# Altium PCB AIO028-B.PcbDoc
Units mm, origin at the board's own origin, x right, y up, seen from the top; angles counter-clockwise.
Board outline 85 x 50 mm, 2 copper layers (TopLayer, BottomLayer); 12 components, 10 nets, 62 pads, 55 vias.
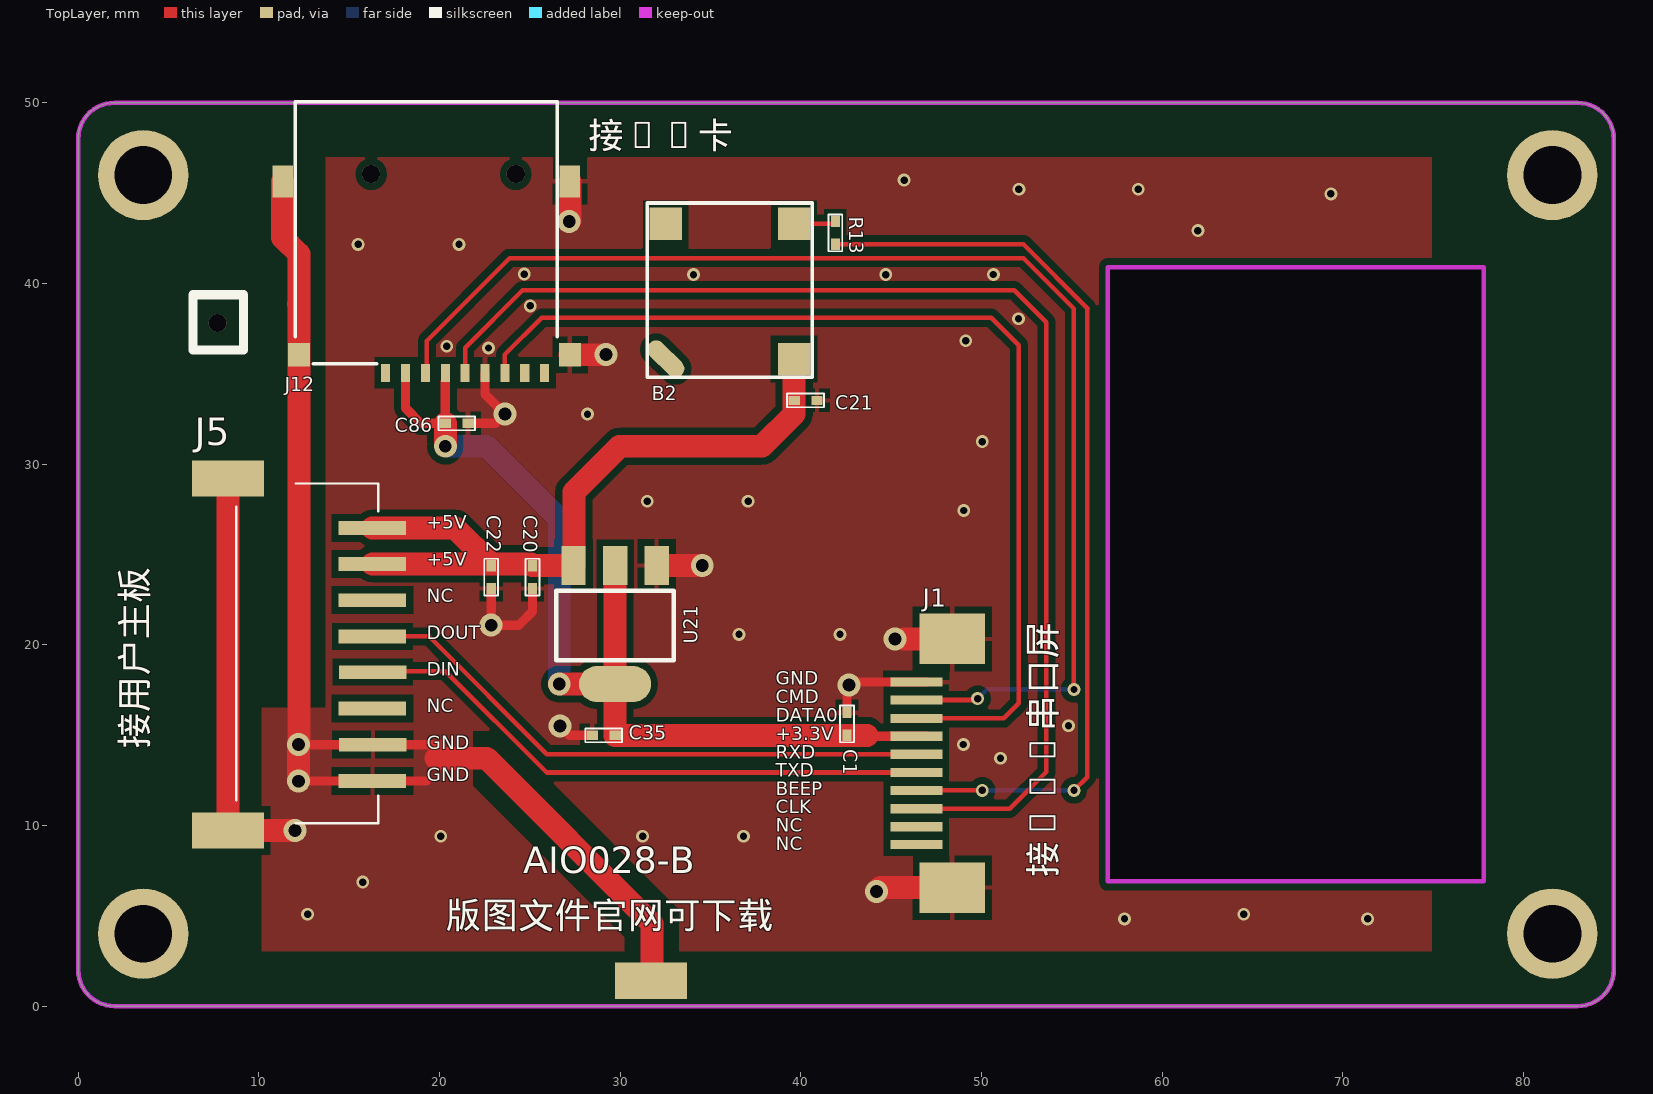
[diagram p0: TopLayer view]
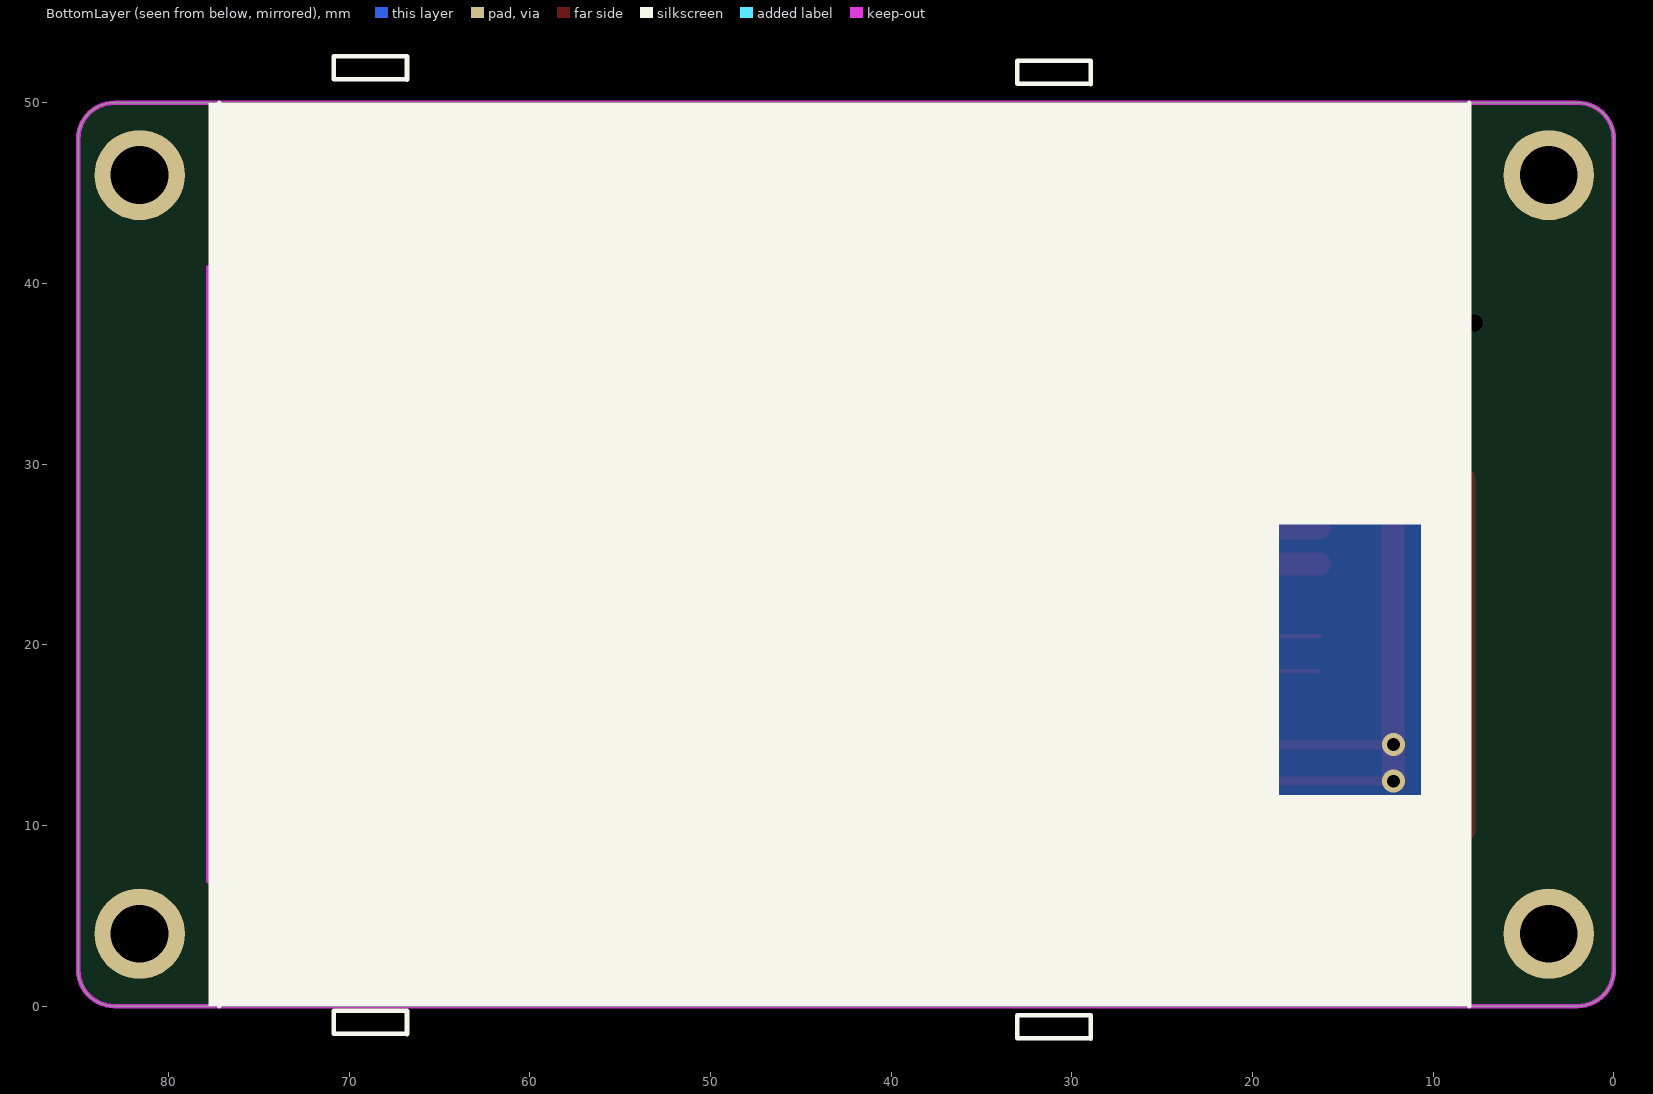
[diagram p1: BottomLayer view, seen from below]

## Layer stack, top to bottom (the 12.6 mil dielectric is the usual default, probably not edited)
TopLayer: signal copper 0.0356
Dielectric: dielectric 0.32, FR-4, Dk 4.8
BottomLayer: signal copper 0.0356

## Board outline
0,2 0,48 cw(c2,48) 2,50 83,50 cw(c83,48) 85,48 85,2 cw(c83,2) 83,0 2,0 cw(c2,2)
cut-out: 57,6.9 77.8,6.9 77.8,40.9 57,40.9

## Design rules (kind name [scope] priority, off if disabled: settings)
Clearance Clearance_polygon [InPolygon] p1: gap=0.381
Clearance [All] p2: gap=0.254
FabricationTestPointUsage TestPointUsage [All] p1: valid=0 allowmultiple=FALSE
FabricationTestpoint Testpoint [All] p1: side=3 testpointundercomponent=TRUE minsize=1.016 maxsize=2.54 preferedsize=1.524 minholesize=0.508 maxholesize=1.016 preferedholesize=0.813 testpointgrid=0.025 allowsidetop=TRUE allowsidebottom=TRUE usegrid=TRUE gridtolerance=0
HoleSize [All] p1: absolutevalues=TRUE maxlimit=7.62 minlimit=0.025 maxpercent=80.000 minpercent=20.000
PolygonConnect PolygonConnect_InPlygon [IsPoly vs InComponent('B2','C1','C20','C21','C22','C35','C86','J1','J12','J5','R13','U21')] p1: connectstyle=Relief reliefconductorwidth=0.254 reliefentries=4 polygonreliefangle="90 Angle"
PolygonConnect [All] p2: connectstyle=Direct reliefconductorwidth=0.254 reliefentries=4 polygonreliefangle="90 Angle"
RoutingVias [All] p1: holewidth=0.711 width=1.27 viastyle="Through Hole" minholewidth=0.711 minwidth=1.27 maxholewidth=0.711 maxwidth=1.27
SilkToSilkClearance [All] p1: silktosilkclearance=0
SilkscreenOverComponentPads [All] p1: minsilkscreentomaskgap=0
SolderMaskExpansion [All] p1: expansion=0.102
Width [All] p1: maxlimit=1.27 minlimit=0.152 preferedwidth=0.508 minimp=50.000000 maximp=50.000000 favimp=50.000000
23 further rules are at their usual default settings.

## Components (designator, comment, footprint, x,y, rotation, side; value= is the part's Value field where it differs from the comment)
B2 "KLJ-8530" BEEP 39.624,35.814 r90 top
C1 "4.7uF/6.3V" 0402A 42.556,14.986 r90 top
C20 "4.7uF/6.3V" 0402A 25.146,24.384 r270 top
C21 "4.7uF/6.3V" 0402A 39.624,33.528 r0 top
C22 "4.7uF/6.3V" 0402A 22.86,24.384 r270 top
C35 "4.7uF/6.3V" 0402A 29.718,14.986 r180 top
C86 "4.7uF/6.3V" 0402A 20.32,32.258 r0 top
J1 "FPC1.0-10下接" FPC1.0-10下接 46.4,8.94 r90 top locked
J5 "FPC2.0-8卧贴-带锁扣" FPC2.0-8卧贴-带锁扣 16.286,12.462 r270 top
J12 "TF卡" TF卡 17.018,35.052 r180 top
R13 "62R" 0402A 41.91,43.434 r270 top
U21 "AMS1117-3.3" AMS1117-3.3 29.718,24.384 r180 top

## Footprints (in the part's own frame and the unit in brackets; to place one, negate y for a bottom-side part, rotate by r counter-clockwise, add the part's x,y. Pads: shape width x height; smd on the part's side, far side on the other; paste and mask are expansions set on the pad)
0402A [mil]
  rect 25x20 smd: 1(0,0) 2(50,0)
  silkscreen extent -15,-15 65,15
AMS1117-3.3 [mm]
  rect 1.35x2.15 smd: 1(-2.3,0) 2(0,0) 3(2.3,0)
  oval 4x2 smd: 4(0,6.56)
  silkscreen extent -3.25,1.4 3.25,5.25
BEEP [mm]
  rect 1.8x1.8 smd: 1(0,0) 2(7.5,0) 3(7.5,7.1)
  oval 2.5x1 smd rot 45: 4(0,7.1)
  silkscreen extent -1.02,-1.02 8.64,8.13
FPC1.0-10下接 [mil]
  rect 20x114 smd: 1(0,0) 2(39,0) 3(78,0) 4(118,0) 5(157,0) 6(197,0) 7(236,0) 8(275,0) 9(315,0) 10(354,0)
  rect 110x142 smd: 11(-94,-78) 12(448,-78)
FPC2.0-8卧贴-带锁扣 [mil]
  rect 30x147 smd: 1(0,0) 2(-79,1) 3(-158,0) 4(-237,1) 5(-315,0) 6(-394,0) 7(-473,0) 8(-551,0)
  rect 78x157 smd: 9(108,-315) 10(-659,-315)
  silkscreen extent -648,-297 92,13
TF卡 [mm]
  rect 0.5x1 smd: 1(0,0) 2(-1.1,0) 3(-2.2,0) 4(-3.3,0) 5(-4.4,0) 6(-5.5,0) 7(-6.6,0) 8(-7.7,0) 9(-8.8,0)
  rect 1.2x1.3 smd: 10(4.8,-1) 11(-10.2,-1)
  rect 1.143x1.778 smd: 12(5.7,-10.6) 13(-10.2,-10.6)
  silkscreen extent -9.5,-15 5,-0.5

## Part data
J12: library part TF?

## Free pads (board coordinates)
  round 5 hole 3.2: 0(3.6,4) 0(3.6,46) 1(81.6,4) 1(81.6,46)
  rect 4x2 smd: 0(31.7,1.4)

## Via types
v1: diameter 0.711, hole 0.406, TopLayer to BottomLayer, 38 vias
v2: diameter 1.27, hole 0.711, TopLayer to BottomLayer, 14 vias
v3: diameter 1, hole 1, TopLayer to BottomLayer, 3 vias

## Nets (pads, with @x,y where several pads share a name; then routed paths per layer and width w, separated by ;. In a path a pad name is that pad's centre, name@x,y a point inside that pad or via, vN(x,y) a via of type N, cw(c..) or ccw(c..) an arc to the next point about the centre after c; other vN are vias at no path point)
3.3V: C1.1 C35.1 C86.1 J1.7 J12.2 J12.4 U21.2 U21.4 | length 54.7
  TopLayer w0.508: J12.2 18.118,33.104 18.964,32.258 C86.1 J12.4@20.32,34.569 ; 43.708,14.934 J1.7@47,14.934
  TopLayer w1.27: v2@20.32,31.242 C86.1 ; v2(26.626,17.824) U21.4 ; U21.2 U21.4 ; 43.656,14.986 43.156,14.986 C35.1 U21.4
  BottomLayer w1.27: v2(20.32,30.988) 22.606,30.988 26.626,26.968 v2(26.626,17.824)
5V: B2.1 C20.1 C21.1 C22.1 J5.7 J5.8 U21.3 | length 39.7
  TopLayer w1.27: J5.7 C22.1@22.86,24.476 ; J5.8 20.879,26.457 C22.1@22.86,24.476 ; B2.1 39.624,32.766 37.846,30.988 29.972,30.988 27.432,28.448 27.432,24.398 U21.3 C20.1 25.054,24.476 C22.1@22.86,24.476
BEEP: J1.4 R13.2 | length 51.1
  TopLayer w0.254: R13.2 52.324,42.164 55.88,38.608 55.855,38.583 55.855,12.675 v1(55.118,11.938) ; J1.4 v1@49.95,11.937
  BottomLayer w0.254: v1(50.038,11.938) v1(55.118,11.938)
CLK: J1.3 J12.5 | length 68.6
  TopLayer w0.254: J12.5 21.418,36.448 24.594,39.624 51.816,39.624 53.594,37.846 53.594,12.954 51.561,10.921 J1.3
CMD: J1.9 J12.3 | length 70.9
  TopLayer w0.254: J12.3 19.304,35.052 19.304,36.83 23.876,41.402 52.324,41.402 55.118,38.608 v1(55.118,17.526) ; J1.9 v1@49.961,16.941
  BottomLayer w0.254: v1(49.784,17.018) 50.292,17.526 v1(55.118,17.526)
DAT0: J1.8 J12.7 | length 56.8
  TopLayer w0.254: J12.7 23.618,36.064 25.654,38.1 50.546,38.1 52.07,36.576 52.07,16.764 51.231,15.925 J1.8
GND: C1.2 C20.2 C21.2 C22.2 C35.2 C86.2 J1.10 J1.11 J1.12 J5.1 J5.2 J5.9 J5.10 J12.6 J12.10 J12.11 J12.12 J12.13 pad.0@31.7,1.4 U21.1 | length 123.8
  TopLayer w0.508: v2@12.201,14.469 J5.2 20.075,14.469 ; v2@12.208,12.462 J5.1 19.288,12.462 ; C86.2 23.114,32.258 v2(23.622,32.766) 22.518,33.87 J12.6 ; C22.2 v2(22.86,21.082) 24.384,21.082 25.146,21.844 C20.2@25.146,22.86 ; v2(26.67,15.494) 27.178,14.986 C35.2 ; C1.2 v2@42.556,17.664 ; v2(42.672,17.78) 42.824,17.932 J1.10 J1.10@47,17.932 ; v2(44.196,6.35) v2@44.398,6.552
  TopLayer w1.27: J5.10 J5.9 v2(12.005,9.719) ; J12.12 11.318,42.53 12.218,41.63 12.218,38.836 ; 12.192,38.862 12.218,38.836 ; v2@12.201,14.469 v2(12.192,14.478) v2(12.192,12.446) v2@12.208,12.462 ; v2@12.218,14.504 J12.10 12.218,38.836 ; 19.812,13.716 22.606,13.716 31.75,4.572 31.75,1.45 pad.0@31.7,1.4 ; v2(27.178,43.434) 27.218,43.474 J12.13 ; J12.11 29.194,36.052 v2(29.21,36.068) ; U21.1 v2(34.544,24.384) ; v2@44.398,6.552 J1.11 ; v2@45.719,20.319 J1.12@49.381,20.319
  other v1: 57.912,4.826 71.374,4.826 12.7,5.08 64.516,5.08 15.748,6.858 20.066,9.398 31.242,9.398 36.83,9.398 51.054,13.716 48.997,14.478 54.813,15.519 36.576,20.574 42.164,20.574 49.022,27.432 31.496,27.94 37.084,27.94 50.038,31.242 28.194,32.766 22.708,36.424 20.396,36.525 49.126,36.83 52.045,38.049 25.019,38.76 34.061,40.488 44.704,40.488 24.689,40.513 50.658,40.498 15.494,42.164 21.082,42.164 61.976,42.926 69.342,44.958 52.07,45.212 58.674,45.212 45.72,45.72
  other v2: 45.212,20.32
NetB2_2: B2.2 R13.1 | length 2.3
  TopLayer w0.254: B2.2 41.79,43.314 R13.1
RXD: J1.5 J5.4 | length 32.4
  TopLayer w0.254: J5.4 16.372,18.542 20.32,18.542 25.934,12.928 J1.5
TXD: J1.6 J5.5 | length 32.8
  TopLayer w0.254: J5.5 19.415,20.463 25.934,13.944 J1.6
pads on no net: B2.3 B2.4 J1.1 J1.2 J5.3 J5.6 J12.1 J12.8 J12.9
copper on no net:
  other v3: 7.7,37.8 16.218,46.052 24.218,46.052

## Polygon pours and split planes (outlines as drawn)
GND on BottomLayer "TopLayer-No Net" (solid, remove dead copper, pour order 10): 10.16,46.99 10.16,3.048 74.93,3.048 74.93,46.99
GND on TopLayer "TopLayer-No Net" (solid, remove dead copper, pour order 6): 13.716,46.99 13.716,16.51 10.16,16.51 10.16,3.048 30.226,3.048 30.226,3.81 21.59,12.446 21.844,12.192 21.844,15.24 23.368,15.24 33.02,5.588 33.274,5.334 33.274,3.048 74.93,3.048 74.93,46.99 13.716,46.99

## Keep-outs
KeepOutLayer:
  lines w0.254: 0,2 ccw(c2,2) 2,0 83,0 ccw(c83,2) 85,2 85,48 ccw(c83,48) 83,50 2,50 ccw(c2,48) 0,48 0,2 ; 57,6.9 77.8,6.9 77.8,40.9 57,40.9 57,6.9

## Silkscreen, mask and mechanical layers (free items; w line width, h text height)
TopOverlay:
  lines w0.508: 6.35,36.322 6.35,39.37 9.144,39.37 9.144,36.322 6.35,36.322
  text "接TF卡" at 28.194,46.99 h2.54
  text "+5V" at 19.304,26.162 h1.27
  text "+5V" at 19.304,24.13 h1.27
  text "NC" at 19.304,22.098 h1.27
  text "DOUT" at 19.304,20.066 h1.27
  text "DIN" at 19.304,18.034 h1.27
  text "GND" at 38.608,17.526 h1.27
  text "CMD" at 38.608,16.51 h1.27
  text "NC" at 19.304,16.002 h1.27
  text "DATA0" at 38.608,15.494 h1.27
  text "+3.3V" at 38.608,14.478 h1.27
  text "接用户主板" at 4.318,14.224 h2.54 r90
  text "GND" at 19.304,13.97 h1.27
  text "RXD" at 38.609,13.451 h1.27
  text "TXD" at 38.608,12.435 h1.27
  text "GND" at 19.304,12.192 h1.27
  text "BEEP" at 38.608,11.419 h1.27
  text "CLK" at 38.608,10.414 h1.27
  text "NC" at 38.609,9.398 h1.27
  text "NC" at 38.609,8.382 h1.27
  text "接AIO串口屏" at 54.61,7.112 h2.54 r90
  text "AIO028-B" at 24.638,6.858 h2.54
  text "版图文件官网可下载" at 20.32,3.81 h2.54
BottomOverlay:
  rectangle: 7.874,0 18.542,11.684
  rectangle: 7.874,11.684 10.668,26.67
  rectangle: 8.128,26.67 18.542,50
  rectangle: 18.542,0 77.8,50
  lines w0.254: 8,0 8,50 ; 28.956,-1.816 28.956,-0.508 33.02,-0.508 33.02,-1.778 28.994,-1.778 ; 28.956,51.016 28.956,52.324 33.02,52.324 33.02,51.054 28.994,51.054 ; 66.802,-1.562 66.802,-0.254 70.866,-0.254 70.866,-1.524 66.84,-1.524 ; 66.802,51.27 66.802,52.578 70.866,52.578 70.866,51.308 66.84,51.308 ; 77.2,0 77.2,50
BottomSolder:
  rectangle: 10.542,11.67 18.542,26.67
